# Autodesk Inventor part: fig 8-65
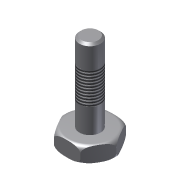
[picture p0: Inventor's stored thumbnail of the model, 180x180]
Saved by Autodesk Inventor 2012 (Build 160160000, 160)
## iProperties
Shininess: 77.0
Length Units: 11269
Angle Units: 11279
Time Units: 11290
Mass Units: 11283
Length Display Precision: 3
Angle Display Precision: 2
Created: 2002-01
Part Number: fig 8-65
Document SubType Name: Modeling
Designer: ***
Density: 1 g/cm^3
Material: Default
Density: 0.0
Volumn: 0.0
Area: 0.0
PropertySet Name: Model Information
Control State: 0
Master: False
Checked Out: False
Author: ***
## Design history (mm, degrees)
sketch "Sketch1"
  geometry: C1 r 25 at (0, 0)
  constraints: 1 centre point
  dimensions: "d0" = 50 diameter of C1
extrude "Extrusion1" new body sketch "Sketch1" distance "d1" = 15; taper "d2" = 0 deg
fillet "Fillet1" dims "d3" = 5
sketch "Sketch2"
  geometry: L1 (25.058, 0)-(12.529, -21.701); L2 (12.529, -21.701)-(-12.529, -21.701); L3 (-12.529, -21.701)-(-25.058, 0); L4 (-25.058, 0)-(-12.529, 21.701); L5 (-12.529, 21.701)-(12.529, 21.701); L6 (12.529, 21.701)-(25.058, 0); 1 further point
  constraints: 12 end point, 11 other
extrude "Extrusion2" sketch "Sketch2" stored distance "d4" = 15; taper "d5" = 0 deg
sketch "Sketch3"
  geometry: C1 r 10.044 at (0, 0); 1 further point
  constraints: 1 centre point, 1 coincident
extrude "Extrusion3" join sketch "Sketch3" distance "d6" = 75; taper "d7" = 0 deg
chamfer "Chamfer1" distance "d8" = 2; stored, may be unused: second distance "d9" = 2, angle "d16" = 45 deg
thread "Thread3" dims "d14" = 30, "d15" = 20
body "Solid1"
